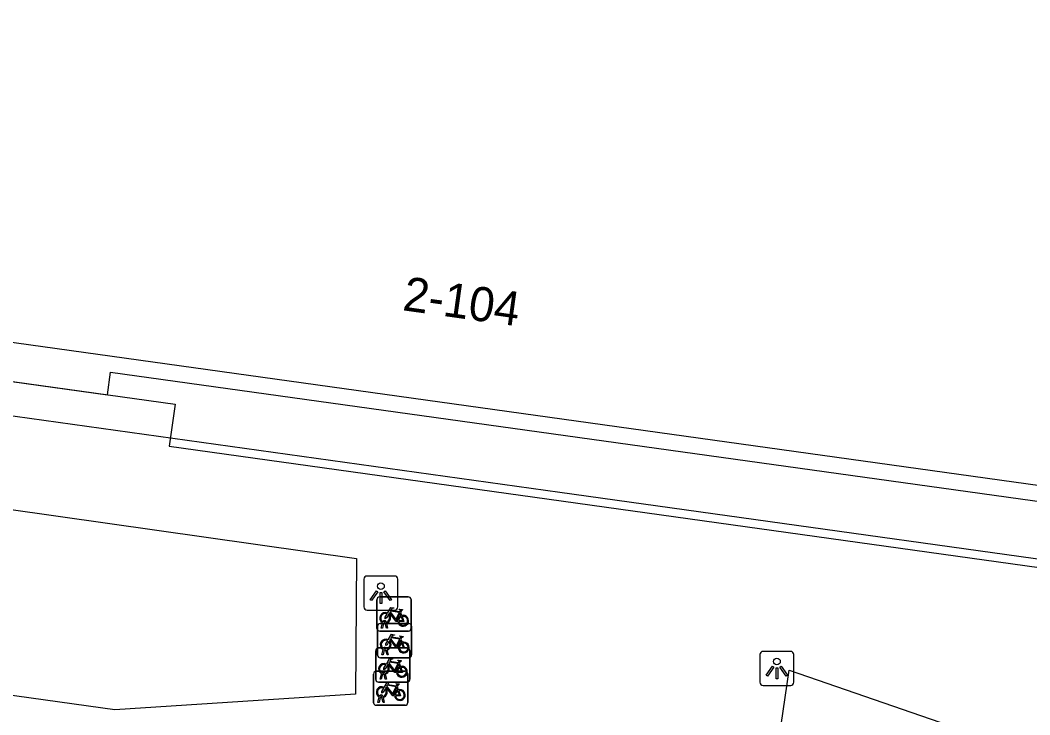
# Model space of a CAD drawing. Extents: x 155640 to 156810, y 382822 to 384046.
# Drawn here: x 156460.76 to 156490.33, y 383672.23 to 383692.57 of the extents above; entities that cross this region are included whole.
import ezdxf

# ---------------------------------------------------------------- set-up
doc = ezdxf.new("R2010")
doc.units = 0
for name, color, linetype in [('IMGEO_Fietsenrek', 7, 'Continuous'), ('IMGEO_Lichtpunt', 7, 'Continuous'), ('IMGEO_Lijnafwatering', 7, 'Continuous'), ('IMGEO_Pand', 7, 'Continuous'), ('IMGEO_Pand_nummerreeks', 7, 'Continuous'), ('IMGEO_Pand_overbouw', 7, 'Continuous'), ('IMGEO_Voetgangersgebied_open', 7, 'Continuous'), ('IMGEO_Voetpad_open', 7, 'Continuous')]:
    doc.layers.add(name, color=color, linetype=linetype)

msp = doc.modelspace()

# ---------------------------------------------------------------- linework, layer by layer
at = {"layer": 'IMGEO_Fietsenrek'}
for p, q in [((156471.212, 383674.761), (156471.212, 383675.602)), ((156471.212, 383675.602), (156471.212, 383674.761)), ((156471.287, 383675.686), (156472.128, 383675.686)), ((156472.128, 383675.686), (156471.287, 383675.686)), ((156472.212, 383675.611), (156472.212, 383674.77)), ((156472.212, 383674.77), (156472.212, 383675.611)), ((156471.899, 383675.235), (156471.935, 383675.14)), ((156471.303, 383674.902), (156472.144, 383674.902)), ((156472.144, 383674.902), (156471.303, 383674.902)), ((156471.339, 383674.77), (156471.378, 383674.93)), ((156471.408, 383674.918), (156471.373, 383674.77)), ((156471.45, 383674.942), (156471.449, 383674.946)), ((156471.491, 383674.77), (156471.457, 383674.912)), ((156471.481, 383674.953), (156471.482, 383674.946)), ((156471.489, 383674.916), (156471.524, 383674.77)), ((156471.228, 383673.977), (156471.228, 383674.818)), ((156471.228, 383674.818), (156471.228, 383673.977)), ((156472.137, 383674.686), (156471.296, 383674.686)), ((156471.296, 383674.686), (156472.137, 383674.686)), ((156471.373, 383674.77), (156471.339, 383674.77)), ((156471.524, 383674.77), (156471.491, 383674.77)), ((156472.228, 383674.827), (156472.228, 383673.986)), ((156472.228, 383673.986), (156472.228, 383674.827)), ((156471.915, 383674.451), (156471.951, 383674.356)), ((156471.175, 383673.267), (156471.175, 383674.108)), ((156471.175, 383674.108), (156471.175, 383673.267)), ((156471.25, 383674.192), (156472.091, 383674.192)), ((156472.091, 383674.192), (156471.25, 383674.192)), ((156471.355, 383673.986), (156471.394, 383674.146)), ((156471.389, 383673.986), (156471.355, 383673.986)), ((156471.424, 383674.134), (156471.389, 383673.986)), ((156471.466, 383674.158), (156471.465, 383674.162)), ((156471.507, 383673.986), (156471.473, 383674.128)), ((156471.497, 383674.169), (156471.498, 383674.162)), ((156471.505, 383674.132), (156471.54, 383673.986)), ((156471.54, 383673.986), (156471.507, 383673.986)), ((156472.175, 383674.117), (156472.175, 383673.276)), ((156472.175, 383673.276), (156472.175, 383674.117)), ((156472.153, 383673.902), (156471.312, 383673.902)), ((156471.312, 383673.902), (156472.153, 383673.902)), ((156471.862, 383673.741), (156471.898, 383673.646)), ((156471.114, 383672.585), (156471.114, 383673.426)), ((156471.114, 383673.426), (156471.114, 383672.585)), ((156471.189, 383673.51), (156472.03, 383673.51)), ((156472.03, 383673.51), (156471.189, 383673.51)), ((156471.302, 383673.276), (156471.341, 383673.436)), ((156471.371, 383673.424), (156471.336, 383673.276)), ((156471.413, 383673.448), (156471.412, 383673.452)), ((156471.454, 383673.276), (156471.42, 383673.418)), ((156471.444, 383673.459), (156471.445, 383673.452)), ((156471.452, 383673.422), (156471.487, 383673.276)), ((156472.114, 383673.435), (156472.114, 383672.594)), ((156472.114, 383672.594), (156472.114, 383673.435)), ((156472.1, 383673.192), (156471.259, 383673.192)), ((156471.259, 383673.192), (156472.1, 383673.192)), ((156471.336, 383673.276), (156471.302, 383673.276)), ((156471.487, 383673.276), (156471.454, 383673.276)), ((156471.801, 383673.059), (156471.837, 383672.964)), ((156472.039, 383672.51), (156471.198, 383672.51)), ((156471.198, 383672.51), (156472.039, 383672.51)), ((156471.241, 383672.594), (156471.28, 383672.754)), ((156471.275, 383672.594), (156471.241, 383672.594)), ((156471.31, 383672.742), (156471.275, 383672.594)), ((156471.352, 383672.766), (156471.351, 383672.77)), ((156471.393, 383672.594), (156471.359, 383672.736)), ((156471.383, 383672.777), (156471.384, 383672.77)), ((156471.391, 383672.74), (156471.426, 383672.594)), ((156471.426, 383672.594), (156471.393, 383672.594))]:
    msp.add_line(p, q, dxfattribs=at)
for points in [[(156471.546, 383675.16), (156471.494, 383675.07), (156471.454, 383675.045), (156471.455, 383675.092), (156471.51, 383675.186)], [(156471.525, 383675.212), (156471.62, 383675.376), (156471.706, 383675.362), (156471.708, 383675.353), (156471.652, 383675.342), (156471.625, 383675.297), (156471.881, 383675.256)], [(156471.821, 383674.968), (156471.771, 383674.968), (156471.58, 383675.219), (156471.561, 383675.187)], [(156471.868, 383675.231), (156471.611, 383675.272), (156471.594, 383675.243), (156471.761, 383675.023), (156471.868, 383675.231)], [(156471.916, 383675.133), (156471.886, 383675.21), (156471.777, 383674.992), (156471.82, 383674.992)], [(156471.881, 383675.256), (156471.906, 383675.305), (156471.9, 383675.309), (156471.877, 383675.313), (156471.865, 383675.32), (156471.864, 383675.323), (156471.866, 383675.328), (156471.961, 383675.313), (156471.963, 383675.303), (156471.953, 383675.29), (156471.941, 383675.284), (156471.927, 383675.29), (156471.899, 383675.235)], [(156471.85, 383674.992), (156471.97, 383674.991), (156471.926, 383675.105)], [(156471.946, 383675.112), (156472.001, 383674.967), (156471.851, 383674.967)], [(156471.541, 383674.428), (156471.636, 383674.592), (156471.722, 383674.578), (156471.724, 383674.569), (156471.668, 383674.558), (156471.641, 383674.513), (156471.897, 383674.472)], [(156471.562, 383674.376), (156471.51, 383674.286), (156471.47, 383674.261), (156471.471, 383674.308), (156471.526, 383674.402)], [(156471.837, 383674.184), (156471.787, 383674.184), (156471.596, 383674.435), (156471.577, 383674.403)], [(156471.884, 383674.447), (156471.627, 383674.488), (156471.61, 383674.459), (156471.777, 383674.239), (156471.884, 383674.447)], [(156471.932, 383674.349), (156471.902, 383674.426), (156471.793, 383674.208), (156471.836, 383674.208)], [(156471.866, 383674.208), (156471.986, 383674.207), (156471.942, 383674.321)], [(156471.962, 383674.328), (156472.017, 383674.183), (156471.867, 383674.183)], [(156471.897, 383674.472), (156471.922, 383674.521), (156471.916, 383674.525), (156471.893, 383674.529), (156471.881, 383674.536), (156471.88, 383674.539), (156471.882, 383674.544), (156471.977, 383674.529), (156471.979, 383674.519), (156471.969, 383674.506), (156471.957, 383674.5), (156471.943, 383674.506), (156471.915, 383674.451)], [(156471.509, 383673.666), (156471.457, 383673.576), (156471.417, 383673.551), (156471.418, 383673.598), (156471.473, 383673.692)], [(156471.488, 383673.718), (156471.583, 383673.882), (156471.669, 383673.868), (156471.671, 383673.859), (156471.615, 383673.848), (156471.588, 383673.803), (156471.844, 383673.762)], [(156471.784, 383673.474), (156471.734, 383673.474), (156471.543, 383673.725), (156471.524, 383673.693)], [(156471.831, 383673.737), (156471.574, 383673.778), (156471.557, 383673.749), (156471.724, 383673.529), (156471.831, 383673.737)], [(156471.879, 383673.639), (156471.849, 383673.716), (156471.74, 383673.498), (156471.783, 383673.498)], [(156471.844, 383673.762), (156471.869, 383673.811), (156471.863, 383673.815), (156471.84, 383673.819), (156471.828, 383673.826), (156471.827, 383673.829), (156471.829, 383673.834), (156471.924, 383673.819), (156471.926, 383673.809), (156471.916, 383673.796), (156471.904, 383673.79), (156471.89, 383673.796), (156471.862, 383673.741)], [(156471.813, 383673.498), (156471.933, 383673.497), (156471.889, 383673.611)], [(156471.909, 383673.618), (156471.964, 383673.473), (156471.814, 383673.473)], [(156471.427, 383673.036), (156471.522, 383673.2), (156471.608, 383673.186), (156471.61, 383673.177), (156471.554, 383673.166), (156471.527, 383673.121), (156471.783, 383673.08)], [(156471.77, 383673.055), (156471.513, 383673.096), (156471.496, 383673.067), (156471.663, 383672.847), (156471.77, 383673.055)], [(156471.783, 383673.08), (156471.808, 383673.129), (156471.802, 383673.133), (156471.779, 383673.137), (156471.767, 383673.144), (156471.766, 383673.147), (156471.768, 383673.152), (156471.863, 383673.137), (156471.865, 383673.127), (156471.855, 383673.114), (156471.843, 383673.108), (156471.829, 383673.114), (156471.801, 383673.059)], [(156471.448, 383672.984), (156471.396, 383672.894), (156471.356, 383672.869), (156471.357, 383672.916), (156471.412, 383673.01)], [(156471.723, 383672.792), (156471.673, 383672.792), (156471.482, 383673.043), (156471.463, 383673.011)], [(156471.818, 383672.957), (156471.788, 383673.034), (156471.679, 383672.816), (156471.722, 383672.816)], [(156471.752, 383672.816), (156471.872, 383672.815), (156471.828, 383672.929)], [(156471.848, 383672.936), (156471.903, 383672.791), (156471.753, 383672.791)]]:
    msp.add_lwpolyline(points, dxfattribs=at)
for centre, radius, start, end in [((156471.29, 383675.608), 0.0779, 92.4484, 184.2845), ((156471.29, 383675.608), 0.0779, 92.4484, 184.2845), ((156472.134, 383675.608), 0.0779, 2.4484, 94.2845), ((156472.134, 383675.608), 0.0779, 2.4484, 94.2845), ((156471.452, 383675.071), 0.159, 62.6766, 242.1369), ((156471.452, 383675.071), 0.129, 63.3192, 238.903), ((156471.452, 383675.071), 0.159, 283.5766, 46.6042), ((156471.306, 383674.824), 0.0779, 92.4484, 184.2845), ((156471.306, 383674.824), 0.0779, 92.4484, 184.2845), ((156471.432, 383674.942), 0.0499, 12.8025, 158.6934), ((156471.452, 383675.071), 0.159, 253.9967, 271.7867), ((156471.432, 383674.942), 0.0174, 12.8025, 163.4502), ((156471.452, 383675.071), 0.129, 253.415, 269.0204), ((156471.452, 383675.071), 0.129, 283.6043, 43.4302), ((156471.979, 383674.987), 0.159, 113.3408, 178.3217), ((156471.979, 383674.987), 0.159, 187.0065, 105.7708), ((156471.979, 383674.987), 0.129, 113.923, 177.9556), ((156471.979, 383674.987), 0.129, 188.6715, 104.5883), ((156472.15, 383674.824), 0.0779, 2.4484, 94.2845), ((156472.15, 383674.824), 0.0779, 2.4484, 94.2845), ((156471.29, 383674.764), 0.0779, 182.4484, 274.2845), ((156471.29, 383674.764), 0.0779, 182.4484, 274.2845), ((156472.134, 383674.764), 0.0779, 272.4484, 4.2845), ((156472.134, 383674.764), 0.0779, 272.4484, 4.2845), ((156471.468, 383674.287), 0.159, 62.6766, 242.1369), ((156471.468, 383674.287), 0.129, 63.3192, 238.903), ((156471.468, 383674.287), 0.129, 283.6043, 43.4302), ((156471.468, 383674.287), 0.159, 283.5766, 46.6042), ((156471.995, 383674.203), 0.159, 113.3408, 178.3217), ((156471.995, 383674.203), 0.159, 187.0065, 105.7708), ((156471.995, 383674.203), 0.129, 113.923, 177.9556), ((156471.995, 383674.203), 0.129, 188.6715, 104.5883), ((156471.253, 383674.114), 0.0779, 92.4484, 184.2845), ((156471.253, 383674.114), 0.0779, 92.4484, 184.2845), ((156471.448, 383674.158), 0.0499, 12.8025, 158.6934), ((156471.468, 383674.287), 0.159, 253.9967, 271.7867), ((156471.448, 383674.158), 0.0174, 12.8025, 163.4502), ((156471.468, 383674.287), 0.129, 253.415, 269.0204), ((156472.097, 383674.114), 0.0779, 2.4484, 94.2845), ((156472.097, 383674.114), 0.0779, 2.4484, 94.2845), ((156472.15, 383673.98), 0.0779, 272.4484, 4.2845), ((156472.15, 383673.98), 0.0779, 272.4484, 4.2845), ((156471.306, 383673.98), 0.0779, 182.4484, 274.2845), ((156471.306, 383673.98), 0.0779, 182.4484, 274.2845), ((156471.415, 383673.577), 0.159, 62.6766, 242.1369), ((156471.415, 383673.577), 0.129, 63.3192, 238.903), ((156471.415, 383673.577), 0.159, 283.5766, 46.6042), ((156471.192, 383673.432), 0.0779, 92.4484, 184.2845), ((156471.192, 383673.432), 0.0779, 92.4484, 184.2845), ((156471.395, 383673.448), 0.0499, 12.8025, 158.6934), ((156471.415, 383673.577), 0.159, 253.9967, 271.7867), ((156471.395, 383673.448), 0.0174, 12.8025, 163.4502), ((156471.415, 383673.577), 0.129, 253.415, 269.0204), ((156471.415, 383673.577), 0.129, 283.6043, 43.4302), ((156471.942, 383673.493), 0.159, 113.3408, 178.3217), ((156471.942, 383673.493), 0.159, 187.0065, 105.7708), ((156471.942, 383673.493), 0.129, 113.923, 177.9556), ((156471.942, 383673.493), 0.129, 188.6715, 104.5883), ((156472.036, 383673.432), 0.0779, 2.4484, 94.2845), ((156472.036, 383673.432), 0.0779, 2.4484, 94.2845), ((156471.253, 383673.27), 0.0779, 182.4484, 274.2845), ((156471.253, 383673.27), 0.0779, 182.4484, 274.2845), ((156472.097, 383673.27), 0.0779, 272.4484, 4.2845), ((156472.097, 383673.27), 0.0779, 272.4484, 4.2845), ((156471.354, 383672.895), 0.159, 62.6766, 242.1369), ((156471.354, 383672.895), 0.129, 63.3192, 238.903), ((156471.334, 383672.766), 0.0499, 12.8025, 158.6934), ((156471.354, 383672.895), 0.129, 283.6043, 43.4302), ((156471.354, 383672.895), 0.159, 283.5766, 46.6042), ((156471.881, 383672.811), 0.159, 113.3408, 178.3217), ((156471.881, 383672.811), 0.159, 187.0065, 105.7708), ((156471.881, 383672.811), 0.129, 113.923, 177.9556), ((156471.881, 383672.811), 0.129, 188.6715, 104.5883), ((156471.192, 383672.588), 0.0779, 182.4484, 274.2845), ((156471.192, 383672.588), 0.0779, 182.4484, 274.2845), ((156471.354, 383672.895), 0.159, 253.9967, 271.7867), ((156471.334, 383672.766), 0.0174, 12.8025, 163.4502), ((156471.354, 383672.895), 0.129, 253.415, 269.0204), ((156472.036, 383672.588), 0.0779, 272.4484, 4.2845), ((156472.036, 383672.588), 0.0779, 272.4484, 4.2845)]:
    msp.add_arc(centre, radius, start, end, dxfattribs=at)
at = {"layer": 'IMGEO_Lichtpunt'}
for p, q in [((156470.828, 383676.202), (156470.828, 383675.395)), ((156470.828, 383676.202), (156470.828, 383675.395)), ((156471.73, 383676.297), (156470.922, 383676.297)), ((156471.73, 383676.297), (156470.922, 383676.297)), ((156471.824, 383675.395), (156471.824, 383676.202)), ((156471.824, 383675.395), (156471.824, 383676.202)), ((156470.922, 383675.301), (156471.73, 383675.301)), ((156470.922, 383675.301), (156471.73, 383675.301)), ((156482.425, 383673.994), (156482.425, 383673.187)), ((156482.425, 383673.994), (156482.425, 383673.187)), ((156483.327, 383674.089), (156482.519, 383674.089)), ((156483.327, 383674.089), (156482.519, 383674.089)), ((156483.421, 383673.187), (156483.421, 383673.994)), ((156483.421, 383673.187), (156483.421, 383673.994)), ((156482.519, 383673.093), (156483.327, 383673.093)), ((156482.519, 383673.093), (156483.327, 383673.093))]:
    msp.add_line(p, q, dxfattribs=at)
for points in [[(156471.202, 383675.866), (156471.241, 383675.838), (156471.053, 383675.576), (156471.015, 383675.603), (156471.202, 383675.866)], [(156471.304, 383675.818), (156471.351, 383675.818), (156471.351, 383675.496), (156471.304, 383675.496), (156471.304, 383675.818)], [(156471.414, 383675.838), (156471.452, 383675.865), (156471.639, 383675.603), (156471.6, 383675.575), (156471.414, 383675.838)], [(156482.799, 383673.658), (156482.838, 383673.63), (156482.65, 383673.368), (156482.612, 383673.395), (156482.799, 383673.658)], [(156482.901, 383673.61), (156482.948, 383673.61), (156482.948, 383673.288), (156482.901, 383673.288), (156482.901, 383673.61)], [(156483.011, 383673.63), (156483.049, 383673.657), (156483.236, 383673.395), (156483.197, 383673.367), (156483.011, 383673.63)]]:
    msp.add_lwpolyline(points, dxfattribs=at)
for centre in [(156471.327, 383676), (156482.924, 383673.792)]:
    msp.add_circle(centre, 0.0994, dxfattribs=at)
for centre, start, end in [((156470.922, 383676.202), 90, 180), ((156470.922, 383676.202), 90, 180), ((156471.73, 383676.202), 0, 90), ((156471.73, 383676.202), 0, 90), ((156470.922, 383675.395), 180, 270), ((156470.922, 383675.395), 180, 270), ((156471.73, 383675.395), 270, 0), ((156471.73, 383675.395), 270, 360), ((156482.519, 383673.994), 90, 180), ((156482.519, 383673.994), 90, 180), ((156483.327, 383673.994), 0, 90), ((156483.327, 383673.994), 0, 90), ((156482.519, 383673.187), 180, 270), ((156482.519, 383673.187), 180, 270), ((156483.327, 383673.187), 270, 0), ((156483.327, 383673.187), 270, 360)]:
    msp.add_arc(centre, 0.0946, start, end, dxfattribs=at)
at = {"layer": 'IMGEO_Lijnafwatering'}
for points in [[(156476.564, 383678.741), (156456.412, 383681.551)], [(156496.589, 383675.948), (156476.564, 383678.741)]]:
    msp.add_lwpolyline(points, dxfattribs=at)
at = {"layer": 'IMGEO_Pand'}
msp.add_lwpolyline([(156504.403, 383768.001), (156526.125, 383742.921), (156525.429, 383738.064), (156524.746, 383738.162), (156523.866, 383731.807), (156524.529, 383731.715), (156519.308, 383694.178), (156518.219, 383694.329), (156517.212, 383687.287), (156518.313, 383687.13), (156516.68, 383675.304), (156436.208, 383686.52), (156438.014, 383699.718), (156438.115, 383699.703), (156438.461, 383700.239)], dxfattribs=at)
at = {"layer": 'IMGEO_Pand_overbouw'}
for points in [[(156432.591, 383702.361), (156430.466, 383687.075), (156436.756, 383686.197), (156436.634, 383685.326), (156465.3, 383681.328), (156465.128, 383680.095), (156509.572, 383673.897), (156509.748, 383675.153), (156517.613, 383674.051), (156518.79, 383682.442), (156518.138, 383682.533), (156525.621, 383736.263)], [(156518.219, 383694.329), (156517.212, 383687.287), (156518.313, 383687.13), (156516.68, 383675.304), (156436.208, 383686.52), (156438.014, 383699.718)]]:
    msp.add_lwpolyline(points, dxfattribs=at)
at = {"layer": 'IMGEO_Voetgangersgebied_open'}
for points in [[(156470.582, 383672.839), (156463.534, 383672.374), (156457.719, 383673.188), (156458.914, 383678.465), (156470.617, 383676.809), (156470.582, 383672.839)], [(156485.129, 383664.029), (156484.755, 383669.261), (156482.706, 383669.609), (156483.286, 383673.543), (156497.623, 383668.588), (156496.723, 383662.413), (156485.129, 383664.029)]]:
    msp.add_lwpolyline(points, dxfattribs=at)
at = {"layer": 'IMGEO_Voetpad_open'}
msp.add_lwpolyline([(156438.461, 383700.239), (156438.64, 383701.529), (156432.591, 383702.361), (156430.466, 383687.075), (156436.756, 383686.197), (156436.634, 383685.326), (156463.32, 383681.604), (156463.412, 383682.264), (156509.833, 383675.802), (156509.748, 383675.153), (156517.613, 383674.051)], dxfattribs=at)

# ---------------------------------------------------------------- texts
at = {"layer": 'IMGEO_Pand_nummerreeks'}
msp.add_text('2-104', height=1, rotation=352.0358, dxfattribs=at).set_placement((156471.936, 383684.083))

doc.saveas('drawing.dxf')
